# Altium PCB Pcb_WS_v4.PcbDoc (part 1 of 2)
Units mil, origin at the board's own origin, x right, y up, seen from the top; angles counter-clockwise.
Board outline 3890 x 3890 mil, 2 copper layers (Top Layer, Bottom Layer); 75 components, 61 nets, 248 pads, 370 vias.
Unrouted connection lines stored in the file: 31.
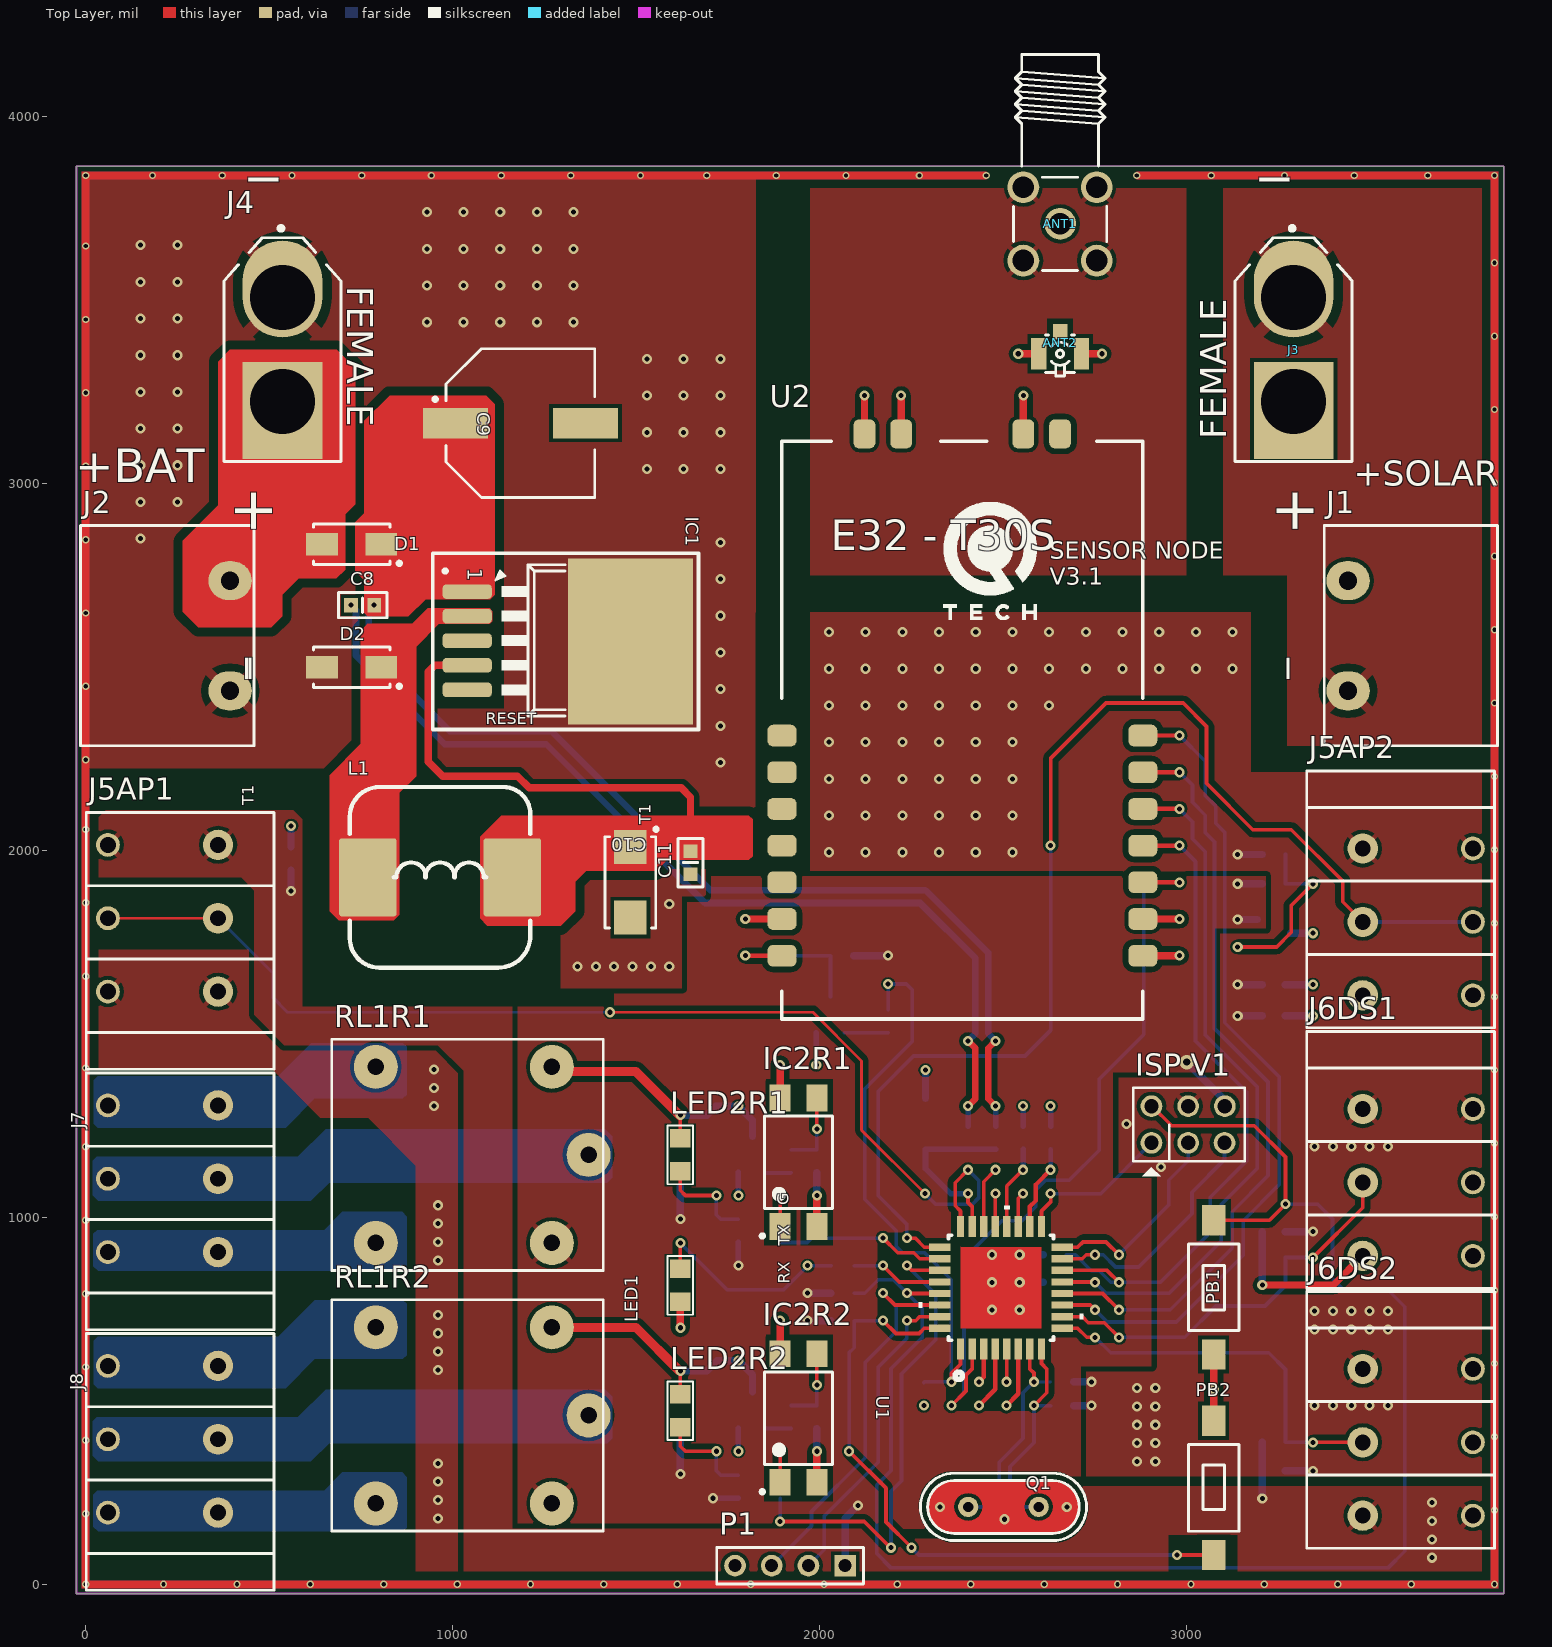
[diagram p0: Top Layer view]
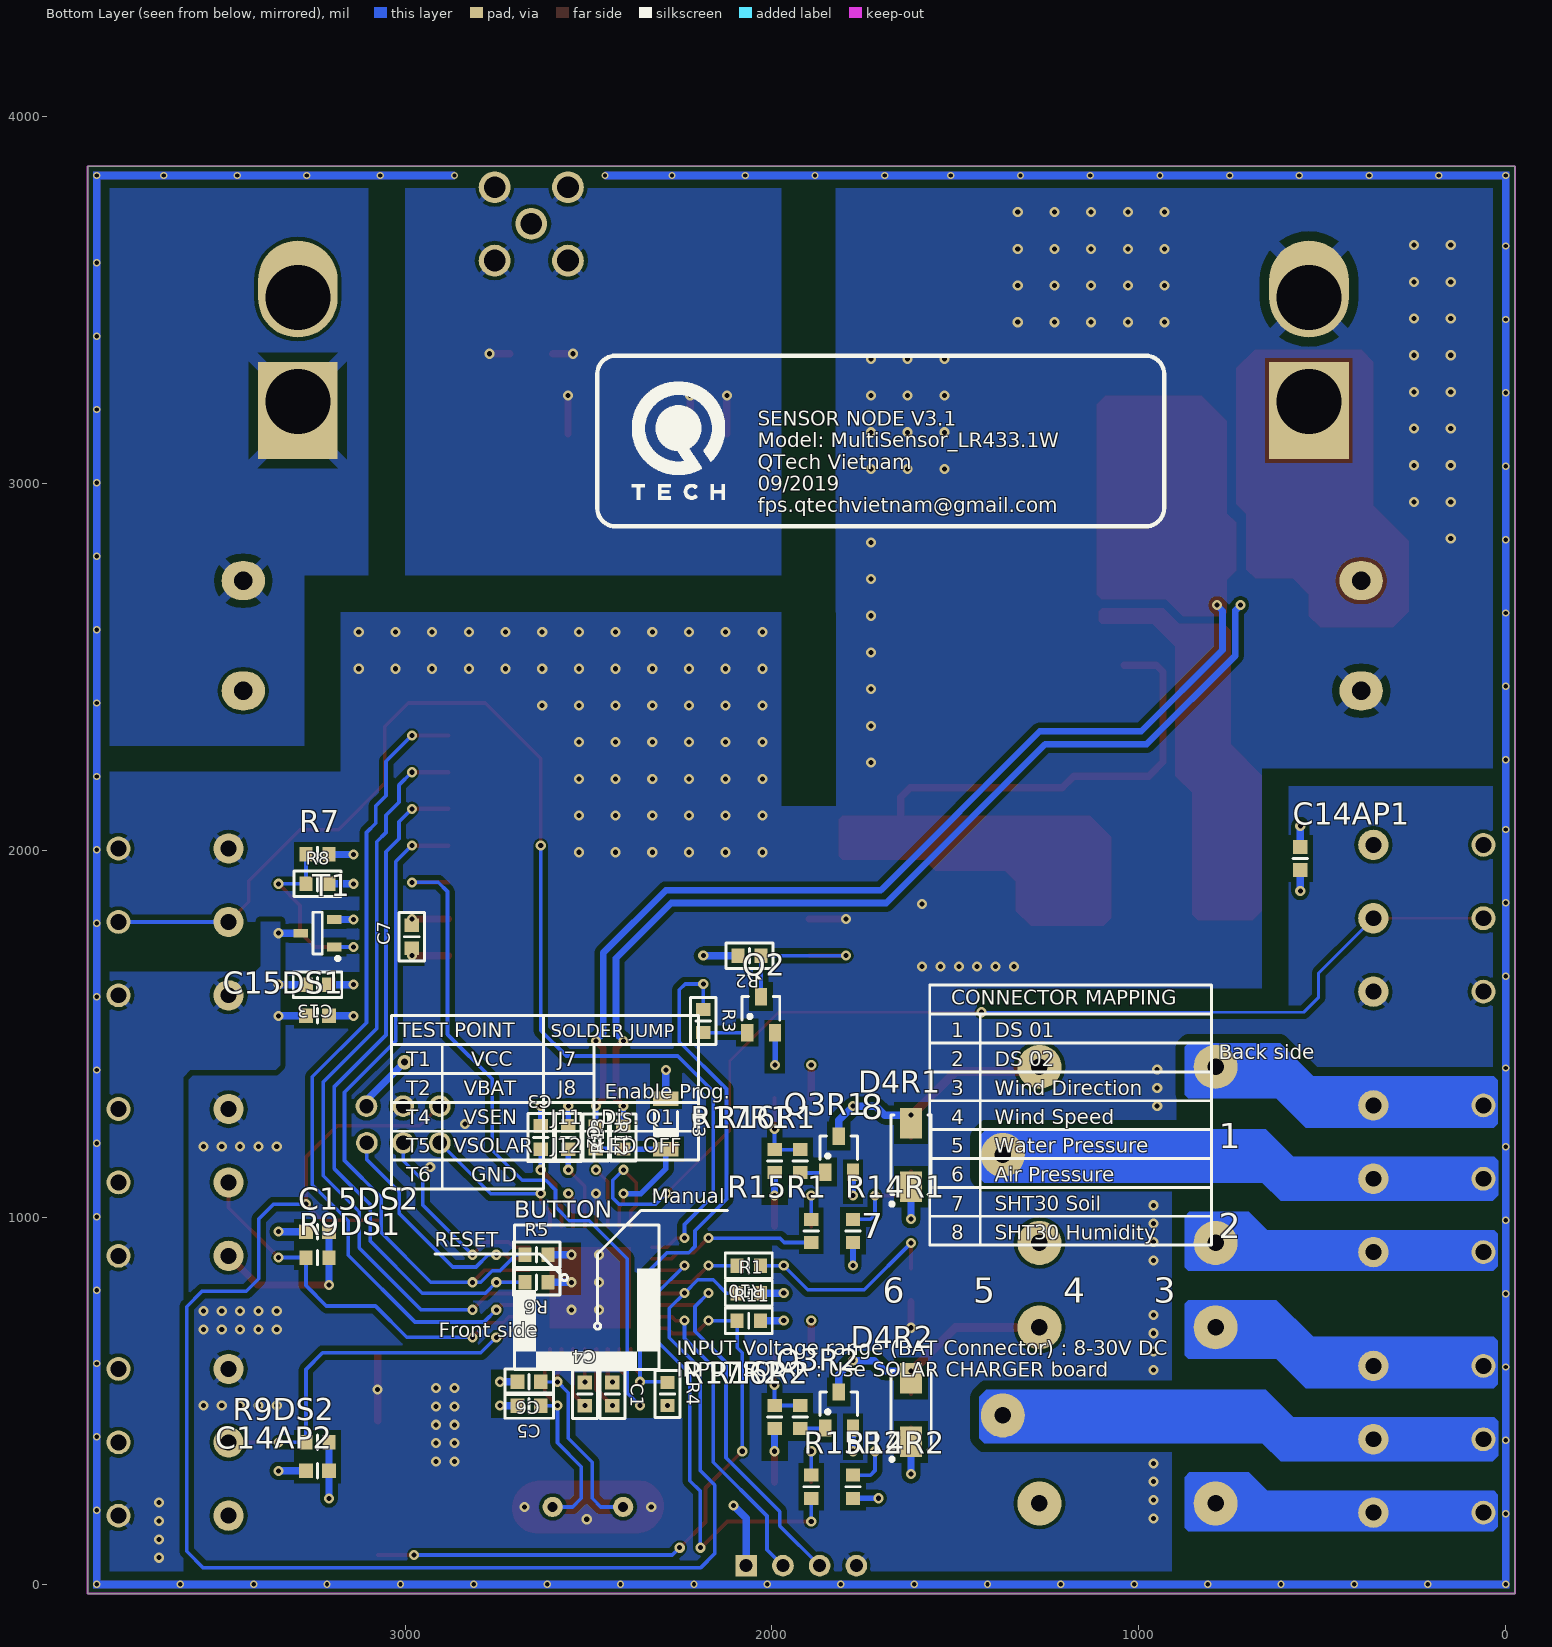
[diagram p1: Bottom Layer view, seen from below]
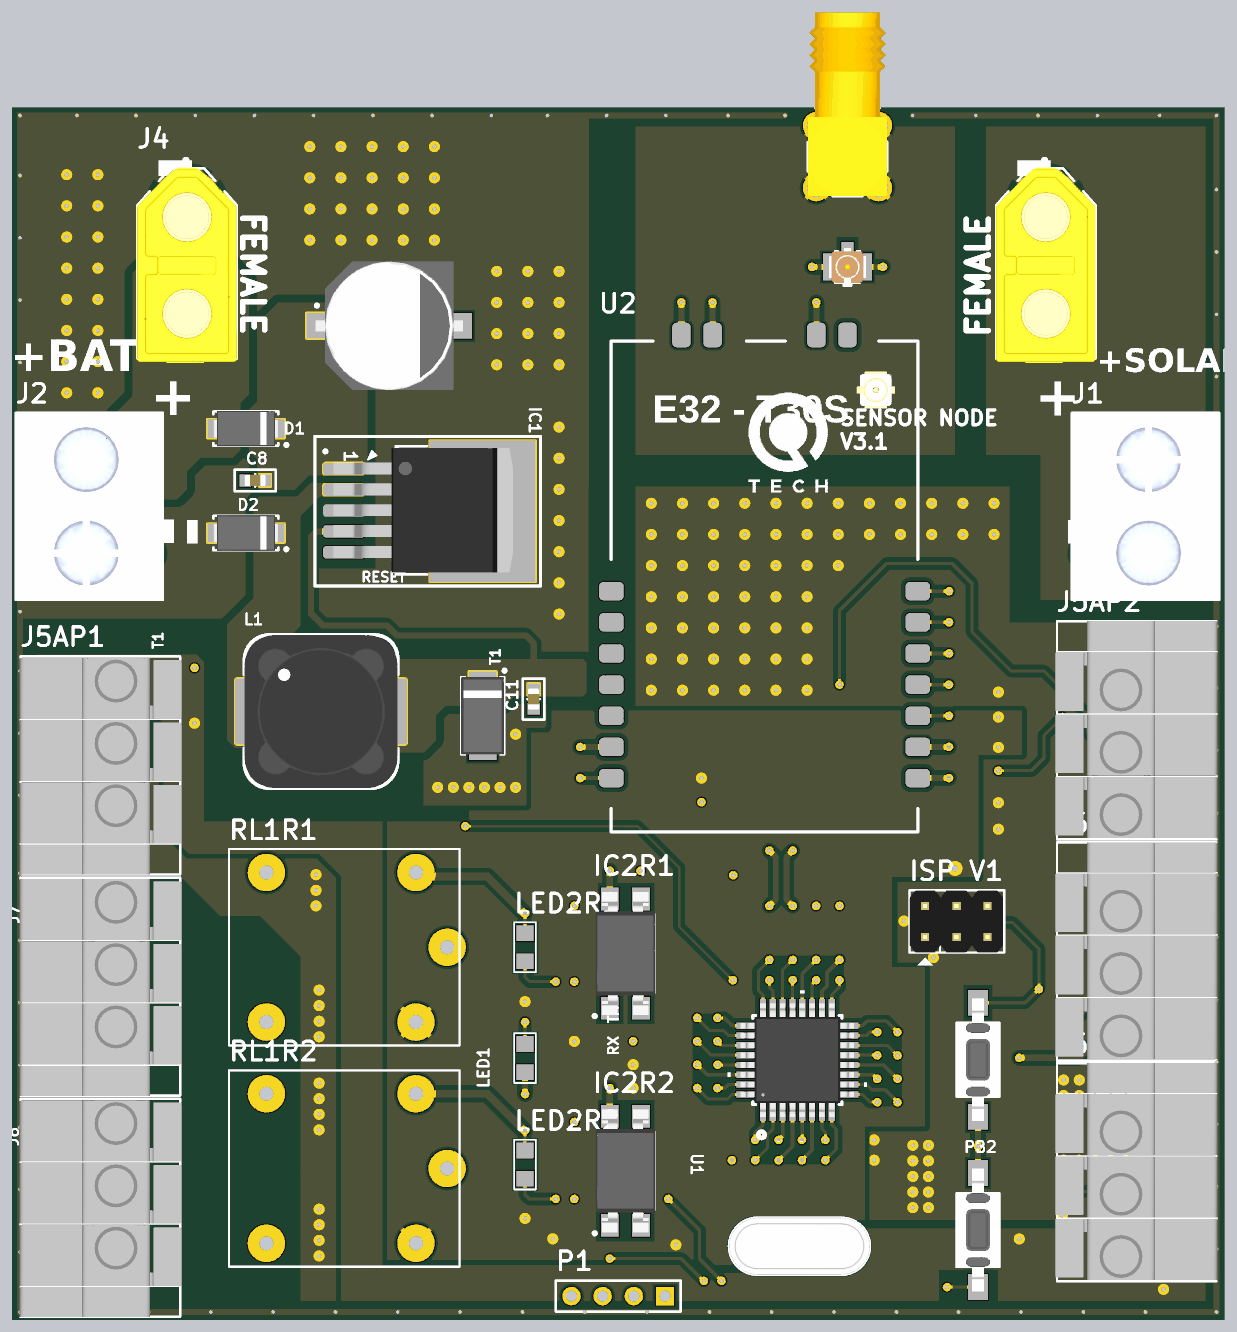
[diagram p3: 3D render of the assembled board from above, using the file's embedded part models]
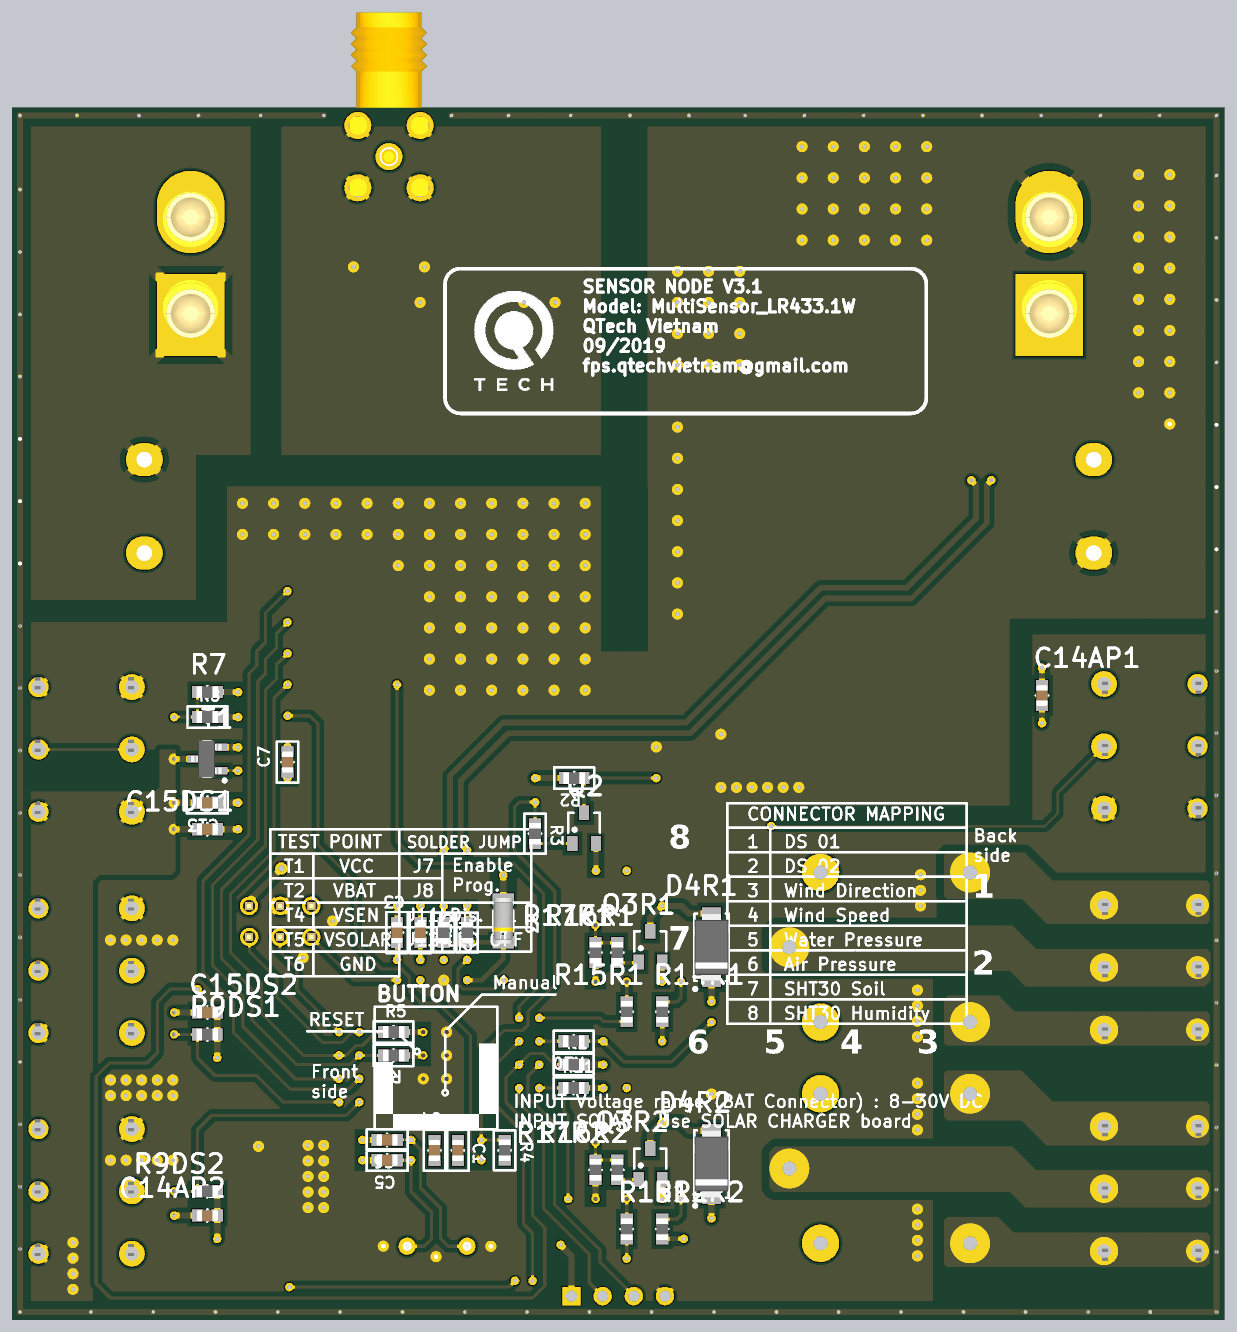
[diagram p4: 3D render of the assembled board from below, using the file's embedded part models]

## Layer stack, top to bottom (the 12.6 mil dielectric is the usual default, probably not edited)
Top Solder: solder mask 0.4, Solder Resist, Dk 3.5
Top Layer: signal copper 1.4
Dielectric 1: dielectric 12.6, FR-4, Dk 4.8
Bottom Layer: signal copper 1.4
Bottom Solder: solder mask 0.4, Solder Resist, Dk 3.5

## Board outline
-25,-25 -25,3865 3865,3865 3865,-25

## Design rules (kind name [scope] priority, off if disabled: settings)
Clearance Keep_Out [OnLayer('Keep-Out Layer')] p1: gap=5 ignorepadtopadclearanceinfootprint=FALSE
Clearance [All] p2: gap=10 ignorepadtopadclearanceinfootprint=FALSE except(5: Via-Poly Via-Region; 15: Track-Poly Track-Region SMDPad-Poly SMDPad-Region Poly-Poly; 25: Poly-Region)
ComponentClearance KF-conn_Clearance [InComponentClass('KF_conn') vs InComponentClass('KF_conn')] p1: gap=5 collisioncheckmode=3 verticalgap=0 showdistances=FALSE
ComponentClearance HS_Comp_Clearance [InComponentClass('HS_Comp') vs IsComponent] p2: gap=165 collisioncheckmode=3 verticalgap=0 showdistances=FALSE
ComponentClearance IC_Comp_Clearance [InComponentClass('IC_Comp') vs IsComponent] p3: gap=150 collisioncheckmode=3 verticalgap=0 showdistances=FALSE
ComponentClearance conn-th_Clearance [InComponentClass('conn-th') vs IsComponent and not InComponentClass('conn-th')] p4: gap=150 collisioncheckmode=3 verticalgap=0 showdistances=FALSE
ComponentClearance chip-ge_Clearance [InComponentClass('chip-ge') vs InAnyComponent] p5: gap=75 collisioncheckmode=3 verticalgap=0 showdistances=FALSE
ComponentClearance chip-0603_Clearance [InComponentClass('chip-0603') vs IsComponent] p6: gap=25 collisioncheckmode=3 verticalgap=0 showdistances=FALSE
PolygonConnect [All] p1: thpad.connectstyle=Relief thpad.reliefconductorwidth=13.78 thpad.reliefentries=4 thpad.polygonreliefangle="45 Angle" thpad.airgapwidth=10 smdpad.connectstyle=NoConnect smdpad.reliefconductorwidth=11.81 smdpad.reliefentries=4 smdpad.polygonreliefangle="45 Angle" smdpad.airgapwidth=10 via.connectstyle=Direct via.reliefconductorwidth=10 via.reliefentries=4 via.polygonreliefangle="90 Angle" via.airgapwidth=10
RoomDefinition Top_Level [InComponentClass('Top_Level')] p1: confinementstyle=ConfineIn formatcopy=TRUE lockcomponents=FALSE outline -1434.14,-1259.46 565.86,-1259.46 565.86,-259.46 -1434.14,-259.46
RoomDefinition R2 [InComponentClass('R2')] p2: confinementstyle=ConfineIn formatcopy=TRUE lockcomponents=FALSE outline -1434.14,-1259.46 565.86,-1259.46 565.86,-259.46 -1434.14,-259.46
RoomDefinition R1 [InComponentClass('R1')] p3: confinementstyle=ConfineIn formatcopy=TRUE lockcomponents=FALSE outline -1434.14,-1259.46 565.86,-1259.46 565.86,-259.46 -1434.14,-259.46
RoomDefinition PWR [InComponentClass('PWR')] p4: confinementstyle=ConfineIn formatcopy=TRUE lockcomponents=FALSE outline -1434.14,-1259.46 565.86,-1259.46 565.86,-259.46 -1434.14,-259.46
RoomDefinition Main [InComponentClass('Main')] p5: confinementstyle=ConfineIn formatcopy=TRUE lockcomponents=FALSE outline -1434.14,-1259.46 565.86,-1259.46 565.86,-259.46 -1434.14,-259.46
RoomDefinition Lora [InComponentClass('Lora')] p6: confinementstyle=ConfineIn formatcopy=TRUE lockcomponents=FALSE outline -1434.14,-1259.46 565.86,-1259.46 565.86,-259.46 -1434.14,-259.46
RoomDefinition DS2 [InComponentClass('DS2')] p7: confinementstyle=ConfineIn formatcopy=TRUE lockcomponents=FALSE outline -1434.14,-1259.46 565.86,-1259.46 565.86,-259.46 -1434.14,-259.46
RoomDefinition DS1 [InComponentClass('DS1')] p8: confinementstyle=ConfineIn formatcopy=TRUE lockcomponents=FALSE outline -1434.14,-1259.46 565.86,-1259.46 565.86,-259.46 -1434.14,-259.46
RoomDefinition AP2 [InComponentClass('AP2')] p9: confinementstyle=ConfineIn formatcopy=TRUE lockcomponents=FALSE outline -1434.14,-1259.46 565.86,-1259.46 565.86,-259.46 -1434.14,-259.46
RoomDefinition AP1 [InComponentClass('AP1')] p10: confinementstyle=ConfineIn formatcopy=TRUE lockcomponents=FALSE outline -1434.14,-1259.46 565.86,-1259.46 565.86,-259.46 -1434.14,-259.46
RoutingVias [All] p1: holewidth=13.78 width=27.56 viastyle="Through Hole" minholewidth=11.81 minwidth=23.62 maxholewidth=19.68 maxwidth=39.37
ShortCircuit [All] p1: allowed=TRUE
SolderMaskExpansion [All] p1: expansion=4 istentingtop=FALSE
Width [All] p1: maxlimit=196.85 minlimit=8 preferedwidth=10
28 further rules are at their usual default settings.

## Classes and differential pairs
component class KF_conn: J5AP1 J5AP2 J6DS1 J6DS2 J7 J8
component class HS_Comp: ANT1 ANT2 Q1
component class IC_Comp: IC1 IC2R1 IC2R2 L1 U1 U2
component class chip-ge: C9 C10 D1 D2 D4R1 D4R2
component class conn-th: "ISP V1" J1 J2 J3 J4 J5AP1 J5AP2 J6DS1 J6DS2 J7 J8 P1 PB1 PB2 RL1R1 RL1R2
component class chip-0603: C1 C2 C3 C4 C5 C6 C7 C8 C11 C13 C14AP1 C14AP2 C15DS1 C15DS2 D3 LED1 LED2R1 LED2R2 Q2 Q3R1 Q3R2 R1 R2 R3 R4 R5 R6 R7 R8 R9DS1 R9DS2 R10 R11 R12 R13 R14R1 R14R2 R15R1 R15R2 R16R1 R16R2 R17R1 R17R2 T1
channel class Sensor_DS18b20_1Wire: DS1 DS2
channel class Sensor_AirPressure_1Wire: AP1 AP2
channel class Relay: R1 R2
component class Top_Level: D3 J7 J8 LED1 P1 PB2 R10 R11 R12 R13
component class R2: D4R2 IC2R2 LED2R2 Q3R2 R14R2 R15R2 R16R2 R17R2 RL1R2
component class R1: D4R1 IC2R1 LED2R1 Q3R1 R14R1 R15R1 R16R1 R17R1 RL1R1
component class Main: C1 C2 C3 C4 C5 C6 "ISP V1" PB1 R1 U1
component class Lora: ANT1 ANT2 C7 Q2 R2 R3 R4 R5 R6 U2
component class DS2: C15DS2 J6DS2 R9DS2
component class DS1: C15DS1 J6DS1 R9DS1
component class AP2: C14AP2 J5AP2
component class AP1: C14AP1 J5AP1
component class PWR: C8 C9 C10 C11 C13 D1 D2 IC1 J1 J2 J3 J4 L1 R7 R8 T1

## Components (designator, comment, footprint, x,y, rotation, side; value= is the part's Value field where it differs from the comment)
ANT1 "Coax_1Female_1Shield" "HUBER-SUHNER_85 SMA-50-0-101/111 NE" 2655.84,3708 r90 top
ANT2 "U.FL" HIROSE_U.FL-R-SMT-1(10) 2655.84,3354 r180 top
C1 "100nF" CAPC1608X87N 2434.61,518.68 r90 bottom
C2 "100nF" CAPC1608X87N 2555,1217.82 r270 bottom
C3 "100nF" CAPC1608X87N 2630,1217.82 r90 bottom
C4 "100nF" CAPC1608X87N 2509.61,518.68 r90 bottom
C5 "100nF" CAPC1608X87N 2661.8,487.18 r0 bottom value=22pF
C6 "100nF" CAPC1608X87N 2661.8,552.18 r0 bottom value=22pF
C7 "100nF" CAPC1608X87N 2981.43,1765 r270 bottom
C8 "100nF" CAPC1608X87N 755,2668.89 r180 top
C9 "470uF" CAPAE1030X1020N 1185,3165 r0 top
C10 "100uF" CAPMP6032X280N 1485,1913.49 r270 top
C11 "100nF" CAPC1608X87N 1648.55,1967 r270 top
C13 "100nF" CAPC1608X87N 3238.5,1634.46 r180 bottom
C14AP1 "100nF" CAPC1608X87N 560,1978.5 r270 bottom (schematic designator C14)
C14AP2 "100nF" CAPC1608X87N 3238.5,309.46 r180 bottom (schematic designator C14)
C15DS1 "100nF" CAPC1608X87N 3238.5,1549.46 r0 bottom (schematic designator C15)
C15DS2 "100nF" CAPC1608X87N 3238.5,961.31 r180 bottom (schematic designator C15)
D1 "SS16" DIOM5127X229N 725,2835 r180 top
D2 "SS16" DIOM5127X229N 725,2500 r180 top
D3 "BZV55-B5V1" DIOMELF3515N 2289.08,1255.22 r90 bottom
D4R1 "BZG03C220" DIOM5326X230N 1620.86,1170.54 r90 bottom (schematic designator D4)
D4R2 "BZG03C220" DIOM5326X230N 1620.86,475 r90 bottom (schematic designator D4)
IC1 "LM2596" TO263-5 1040.04,2705.82 r270 top
IC2R1 "SFH6156-4" SOIC254P977X406-4N 1942.86,1150.54 r90 top (schematic designator IC2)
IC2R2 "SFH6156-4" SOIC254P977X406-4N 1942.86,453.26 r90 top (schematic designator IC2)
"ISP V1" "Connector 3x2" JP3x2 3005,1253.39 r0 top
J1 "CON KF7.62-2P" "CON KF7.62-2P" 3440.86,2585.54 r270 top locked
J2 "CON KF7.62-2P" "CON KF7.62-2P" 393.93,2585.54 r90 top locked
J3 "XT60-FM" XT60-FM 3292.32,3364.99 r270 top locked
J4 "XT60-FM" XT60-FM 536.41,3364.99 r270 top locked
J5AP1 "KF142V-3P" "CON KF142V-3P-5.08" 60.86,2015.54 r270 top (schematic designator J5)
J5AP2 "KF142V-3P" "CON KF142V-3P-5.08" 3780.86,1605.54 r90 top (schematic designator J5)
J6DS1 "KF142V-3P" "CON KF142V-3P-5.08" 3780.86,895.54 r90 top (schematic designator J6)
J6DS2 "KF142V-3P" "CON KF142V-3P-5.08" 3780.86,187.26 r90 top (schematic designator J6)
J7 "KF142V-3P" "CON KF142V-3P-5.08" 60.86,1305.54 r270 top
J8 "KF142V-3P" "CON KF142V-3P-5.08" 60.86,595.54 r270 top
L1 "33uH" L_SMD 769.25,1927 r90 top
LED1 "LED" L-0805 1620.86,815 r270 top value="LED 3 ly Single Colour"
LED2R1 "LED" L-0805 1620.86,1170.54 r90 top value="LED 3 ly Single Colour" (schematic designator LED2)
LED2R2 "LED" L-0805 1620.86,473.26 r90 top value="LED 3 ly Single Colour" (schematic designator LED2)
P1 "Header 4" HDR1X4 2070,51 r180 top
PB1 "Push Button" PB_TYCO_FSMSM 3074.53,809.62 r270 top
PB2 "Push Button" PB_TYCO_FSMSM 3074.53,263.07 r90 top
Q1 "20MHz" XTAL_HC-49/U 2501.55,211.12 r0 top
Q2 "C1815" SOT23-3 2030.2,1552.8 r180 bottom
Q3R1 "C1815" SOT23-3 1817.86,1172.59 r180 bottom (schematic designator Q3)
Q3R2 "C1815" SOT23-3 1817.86,475.31 r180 bottom (schematic designator Q3)
R1 "10k" RESC1608X55N 2063.21,793.79 r0 bottom
R2 "10k" RESC1608X55N 2061.5,1713.49 r0 bottom value=4k7
R3 "10k" RESC1608X55N 2187.06,1535.29 r270 bottom value=1k
R4 "10k" RESC1608X55N 2284.61,518.68 r90 bottom value=1k
R5 "4k7" RESC1608X55N 2641.17,898.39 r180 bottom value=10k
R6 "4k7" RESC1608X55N 2641.17,823.39 r180 bottom value=10k
R7 "1k" RESC1608X55N 3238.5,1989.46 r0 bottom
R8 "10k" RESC1608X55N 3238.5,1909.46 r0 bottom
R9DS1 "4k7" RESC1608X55N 3238.5,890.77 r180 bottom (schematic designator R9)
R9DS2 "4k7" RESC1608X55N 3238.5,387.26 r180 bottom (schematic designator R9)
R10 "10k" RESC1608X55N 2063.21,868.79 r180 bottom value=200
R11 "10k" RESC1608X55N 2063.21,718.79 r0 bottom
R12 "10k" RESC1608X55N 2480,1217.82 r270 bottom value=2M
R13 "10k" RESC1608X55N 2405,1217.82 r90 bottom value=1M
R14R1 "1k" RESC1608X55N 1779.06,963.52 r90 bottom value=200 (schematic designator R14)
R14R2 "1k" RESC1608X55N 1779.06,266.24 r90 bottom value=200 (schematic designator R14)
R15R1 "1k" RESC1608X55N 1892.86,963.52 r90 bottom (schematic designator R15)
R15R2 "1k" RESC1608X55N 1892.86,266.24 r90 bottom (schematic designator R15)
R16R1 "1k" RESC1608X55N 1922.86,1153.52 r270 bottom value=200 (schematic designator R16)
R16R2 "1k" RESC1608X55N 1922.86,456.24 r270 bottom value=200 (schematic designator R16)
R17R1 "10k" RESC1608X55N 1992.86,1153.52 r90 bottom (schematic designator R17)
R17R2 "10k" RESC1608X55N 1992.86,456.24 r90 bottom (schematic designator R17)
RL1R1 "Relay 10A/12V" RL_SPDT_10A 1370.86,1170.54 r180 top value="Relay SPDT, 10A, 12V" (schematic designator RL1)
RL1R2 "Relay 10A/12V" RL_SPDT_10A 1370.86,460.54 r180 top value="Relay SPDT, 10A, 12V" (schematic designator RL1)
T1 "BSH203" SOT95P230X110-3N 3238.5,1774.74 r0 bottom
U1 "ATmega328-AU" 32A_ATM-M 2494.8,808.59 r90 top
U2 "E32-T30S" E32-T30S 2881.43,3115.85 r180 top

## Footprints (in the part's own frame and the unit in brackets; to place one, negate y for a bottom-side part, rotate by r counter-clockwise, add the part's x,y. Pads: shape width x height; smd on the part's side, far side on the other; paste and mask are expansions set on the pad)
32A_ATM-M [mil]
  rect 58x20 smd: 1(-167,110.24) 2(-167,78.74) 3(-167,47.24) 4(-167,15.75) 5(-167,-15.75) 6(-167,-47.24) 7(-167,-78.74) 8(-167,-110.24) 17(167,-110.24) 18(167,-78.74) 19(167,-47.24) 20(167,-15.75) 21(167,15.75) 22(167,47.24) 23(167,78.74) 24(167,110.24)
  rect 20x58 smd: 9(-110.24,-167) 10(-78.74,-167) 11(-47.24,-167) 12(-15.75,-167) 13(15.75,-167) 14(47.24,-167) 15(78.74,-167) 16(110.24,-167) 25(110.24,167) 26(78.74,167) 27(47.24,167) 28(15.75,167) 29(-15.75,167) 30(-47.24,167) 31(-78.74,167) 32(-110.24,167)
  silkscreen extent -250,-224 224,224, body extent -182,-182 182,182, height 47
CAPAE1030X1020N [mm] "Capacitor, Aluminium Electrolytric, 10.3mm L X 10.3mm W X 10.2mm H, IPC Medium Density"
  rect 4.5x2.1 smd: 1(-4.5,0) 2(4.5,0)
  silkscreen extent -6.02,-5.15 5.15,5.15, body extent -6,-5.25 6,5.25, height 10.2
CAPC1608X87N [mm] "Chip Capacitor, Body 1.6x0.8mm IPC Medium Density"
  rect 0.95x1 smd: 1(-0.8,0) 2(0.8,0)
  silkscreen extent -1.68,-0.87 1.68,0.87, body extent -0.87,-0.47 0.88,0.48, height 0.87
CAPMP6032X280N [mm] "Capacitor, Polarized, Molded  Body 6.0x3.2mm, IPC Medium Density"
  rect 2.35x2.25 smd: 1(-2.45,0) 2(2.45,0)
  silkscreen extent -3.8,-1.75 3.15,1.9, body extent -3.15,-1.75 3.15,1.75, height 2.8
"CON KF7.62-2P" [mm]
  oval 2.7x3 hole 1.26: 1(-3.81,0) 2(3.81,0)
  silkscreen extent -7.62,-1.65 7.62,10.35, body extent -7.62,-1.65 7.62,10.35, height 12.4
"CON KF142V-3P-5.08" [mm]
  round 2.1 hole 1.1: 1(0,7.62) 2(5.08,7.62) 3(10.16,7.62)
  round 1.65 hole 1.1: 1(0,0) 2(5.08,0) 3(10.16,0)
  silkscreen extent -2.25,-1.5 15.53,11.5, body extent -2.14,-1.57 15.54,11.63, height 14.23
DIOM5127X229N [mm] "DO-214-AC/SMA Molded Diode, 2-Leads, Body 5.1x2.7mm, IPC Medium Density"
  rect 2.2x1.55 smd: 1(-2.05,0) 2(2.05,0)
  silkscreen extent -3.43,-1.4 2.65,1.45, body extent -2.67,-1.45 2.68,1.45, height 2.29
DIOM5326X230N [mm] "DO-214-AC/SMA Molded Diode, Body 5.3x2.6mm, IPC Medium Density"
  rect 2.1x1.55 smd: 1(-2.2,0) 2(2.2,0)
  silkscreen extent -3.52,-1.4 2.75,1.45, body extent -2.75,-1.4 2.75,1.4, height 2.3
DIOMELF3515N [mm] "SOD80C, MELF Diode, 2-Leads, Body 3.5x1.5mm, IPC Medium Density"
  rect 1x1.75 smd: 1(-1.75,0) 2(1.75,0)
  silkscreen extent -0.85,-0.8 0.85,0.8, body extent -1.85,-0.8 1.85,0.8, height 1.6
E32-T30S [mm] "Lora-EBYTE-21~30dBm-UART-SX1278-25x40mm"
  rrect50% 2x1.5 smd: 1(0,20.38) 2(0,22.92) 3(0,25.46) 4(0,28) 5(0,30.54) 6(0,33.08) 7(0,35.62) 8(24.98,35.62) 9(24.98,33.08) 10(24.98,30.54) 11(24.98,28) 12(24.98,25.46) 13(24.98,22.92) 14(24.98,20.38)
  rrect50% 1.5x2 smd: 15(19.27,-0.5) 16(16.73,-0.5) 17(8.27,-0.5) 18(5.73,-0.5)
  silkscreen extent 0,0 25,40, body extent 0,0 25,40, height 3.5
HDR1X4 [mm] "Connector; Header; 4 Position"
  rect 1.5x1.5 hole 0.9: 1(0,0)
  round 1.5 hole 0.9: 2(2.54,0) 3(5.08,0) 4(7.62,0)
  silkscreen extent -1.27,-1.27 8.89,1.27
HIROSE_U.FL-R-SMT-1(10) [mm] "Up to 6GHz Ultra Small Surface Mount Male Coaxial Connectors U.FL Series"
  rect 1x1.05 smd: 1(0,-1.525)
  rect 1.05x2.2 smd: 2(-1.475,0) 2(1.475,0)
  silkscreen extent -1,-1.3 1,1.55, body extent -1.5,-1.55 1.5,1.55, height 1.25
"HUBER-SUHNER_85 SMA-50-0-101/111 NE" [mm] "50 Ohm SMA Right Angle PCB Jack"
  round 2.2 hole 1.5: 1(0,0) 2(-2.54,-2.54) 2(-2.54,2.54) 2(2.54,-2.54) 2(2.54,2.54)
  silkscreen extent -3.23,-3.23 11.73,3.23, body extent -3.23,-3.23 11.73,3.23, height 9.6
JP3x2 [mm] "Connector 3x2"
  round 1.5 hole 1: 1(-2.54,-1.27) 2(0,-1.27) 3(2.515,-1.27) 4(-2.54,1.27) 5(0,1.27) 6(2.54,1.27)
  silkscreen extent -3.81,-3.58 3.91,2.54, body extent -3.81,-2.54 3.81,2.54, height 8.52
L-0805 [mil] "Compoment SMD 80x50mil"
  rect 50x55 smd: 1(-45,0) 2(45,0)
  silkscreen extent -80,-35 80,35, body extent -50,-20 50,20, height 43
L_SMD [mm]
  rrect10% 5.4x4 smd mask+0.1: 1(0,0) 2(0,-10)
  silkscreen extent -6.25,-11.25 6.25,1.25, body extent -6.25,-11.25 6.25,1.25, height 6.7
PB_TYCO_FSMSM [mm] "Body 3.5x6.0mm, Pushbutton Switch,  TYCO FSMSM Serie"
  rect 2.1x1.6 smd: 1(-4.65,0) 2(4.65,0)
  silkscreen extent -3,-1.75 3,1.75, body extent -5,-1.75 5,1.75, height 4.3
RESC1608X55N [mm] "Chip Resistor, EIA 0603, Metric 1608, Body 1.6x0.8mm, IPC Medium Density"
  rect 0.9x1 smd: 1(-0.8,0) 2(0.8,0)
  silkscreen extent -1.63,-0.87 1.63,0.87, body extent -0.87,-0.47 0.88,0.48, height 0.55
RL_SPDT_10A [mil] "Relay SPDT, 5 pin, 10A,W 650mil, L 800mil, H 800mil"
  round 120 hole 45: 1(0,0) 2(580,240) 3(580,-240) 4(100,-240) 5(100,240)
  silkscreen extent -40,-315 700,315
SOIC254P977X406-4N [mm] "SOIC, 2.54mm pitch; 4 pin, 6.65mm W X 4.69mm L, IPC Medium Density"
  rect 1.85x1.45 smd: 1(-4.45,1.27) 2(-4.45,-1.27) 3(4.45,-1.27) 4(4.45,1.27)
  silkscreen extent -5.22,-2.35 3.2,2.62, body extent -5.01,-2.41 5.02,2.42, height 4.06
SOT23-3 [mm] "SOT 23"
  rect 0.85x1.2 smd: 1(-0.94,-1.245) 2(0.985,-1.25) 3(0.005,1.25)
  silkscreen extent -1.29,-0.38 1.31,1.25, body extent -1.5,-1.5 1.52,1.5, height 1.27
SOT95P230X110-3N [mm] "SOT23, 3 pin, Pitch 0.95mm - 1.3mm W X 2.9mm L X 1.1mm H, IPC Medium Density"
  rect 1x0.6 smd: 1(-1.15,0.95) 2(-1.15,-0.95) 3(1.15,0)
  silkscreen extent -1.52,-1.45 0.33,1.87, body extent -1.17,-1.5 1.33,1.5, height 1.1
TO263-5 [mm]
  rrect50% 1x3.4 smd: 1(0,0) 2(1.7,0) 4(5.1,0) 5(6.8,0)
  rrect50% 1x3.4 smd mask+0: 3(3.4,0)
  rect 11.5x8.634 smd: 6(3.45,11.302)
  silkscreen extent -2.66,-2.38 9.54,16.02, body extent -1.71,-0.87 8.45,13.77, height 4.57
XT60-FM [mm]
  oval 6.716x5.516 hole 4.5 copper offset -0.6,0: 1(-3.6,0)
  rect 6.716x5.516 hole 4.5 copper offset 0.6,0: 2(3.6,0)
  silkscreen extent -8.55,-4.05 7.75,4.05, body extent -7.81,-4.07 8.12,4.06, height 15.5
XTAL_HC-49/U [mm] "HC-49/U Leaded Cristal, Body 11.05x4.8mm; Pitch 4.88mm"
  round 1.4 hole 0.7: 1(-2.44,0) 2(2.44,0)
  silkscreen extent -5.75,-2.33 5.75,2.33, body extent -5.75,-2.33 5.75,2.33, height 3.5

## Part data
ANT1: library part HUBER-SUHNER_85_SMA-50-0-101/111_NE, Manufacturer=HUBER+SUHNER, Manufacturer Part Number=85_SMA-50-0-101/111_NE
ANT2: library part HIROSE_U.FL-R-SMT-1(10), Manufacturer="HIROSE (HRS)", Manufacturer Part Number=U.FL-R-SMT-1(10)
C1 C2 C3 C4 C7 C8 C11 C13 C14AP1 C14AP2 C15DS1 C15DS2: library part CC0603_100NF_50V_10%_X7R, "Non-polarised capacitor", Case=0603, Manufacturer=GENERIC, Manufacturer1 ComponentHeight=0.87mm, Manufacturer1 Example=PHYCOMP, Manufacturer1 Part Number=223858615649, Tolerance=±10%, Voltage=50V
C5 C6: library part CC0603_22PF_50V_5%_NP0, "Non-polarised capacitor", Case=0603, Manufacturer=GENERIC, Manufacturer1 ComponentHeight=0.87mm, Manufacturer1 Example=PHYCOMP, Manufacturer1 Part Number=223886715229, Tolerance=±5%, Voltage=50V
C9: library part CAE1030-1020_470UF_25V_20%, "Polarised capacitor", Case=G, Manufacturer=GENERIC, Manufacturer1 ComponentHeight=10.2mm, Manufacturer1 Example=PANASONIC, Manufacturer1 Part Number=EEEFK1E471AP, Tolerance=±20%, Voltage=25V
C10: library part CTE6032-28_100UF_6.3V_10%_LESR0075, "Polarised capacitor", Case=C, Manufacturer=GENERIC, Manufacturer1 ComponentHeight=2.8mm, Manufacturer1 Example=AVX, Manufacturer1 Part Number=TPSC107K006R0075, Tolerance=±10%, Voltage=6.3V
D1 D2: "Schottky Diode", Case=DO-214AC, Manufacturer="VISHAY GENERAL SEMICONDUCTOR", Power=1A, Voltage=60V
D3: "Zener Diode", Case=SOD-80C, Manufacturer="NXP SEMICONDUCTORS", Power=500mW, Voltage=5V1
D4R1 D4R2: "Zener Diode", Case=DO-214AC, Manufacturer="VISHAY SEMICONDUCTOR", Power=1.25W, Voltage=220V
IC1: library part LM2596-5V
IC2R1 IC2R2: "Single Optocoupler", Case=SOIC4, Manufacturer="VISHAY SEMICONDUCTORS"
"ISP V1": library part JP3x2
J3 J4: Package="Package Analog Devices"
J5AP1 J5AP2 J6DS1 J6DS2 J7 J8: library part "CON KF142V-3P-5.08", "CON KF142V-3P-5.08"
L1: library part "L_SMD 33uH"
LED1 LED2R1 LED2R2: "LED Single colour Green and Red"
P1: "Header, 4-Pin"
PB1 PB2: "Push-Button Switch SPDT", Manufacturer="TYCO ELECTRONICS", Manufacturer Part Number="FSMSM or 1437566-3", Part Number=PB_TYCO_FSMSM
Q1: library part XTAL_20MHZ_AEL_HC-49/U, "Quartz Crystal", Manufacturer="AEL CRYSTALS", Manufacturer Part Number=X20M000000L010
Q2 Q3R1 Q3R2: library part 2SC1815, PSpiceTemplate="Q^@REFDES %c %b %e @MODEL"
R1 R5 R6 R8 R11 R17R1 R17R2: library part R0603_10K_1%_0.1W_100PPM, "Resistor - 1%", Case=0603, Manufacturer=GENERIC, Manufacturer1 ComponentHeight=0.55mm, Manufacturer1 Example="NIC COMPONENT", Manufacturer1 Part Number=NRC06F1002TRF, Power=0.1W, Tolerance=±1%
R2 R9DS1 R9DS2: library part R0603_4K7_1%_0.1W_100PPM, "Resistor - 1%", Case=0603, Manufacturer=GENERIC, Manufacturer1 ComponentHeight=0.55mm, Manufacturer1 Example="NIC COMPONENT", Manufacturer1 Part Number=NRC06F4701TRF, Power=0.1W, Tolerance=±1%
R3 R4 R7 R15R1 R15R2: library part R0603_1K_1%_0.1W_100PPM, "Resistor - 1%", Case=0603, Manufacturer=GENERIC, Manufacturer1 ComponentHeight=0.55mm, Manufacturer1 Example="NIC COMPONENT", Manufacturer1 Part Number=NRC06F1001TRF, Power=0.1W, Tolerance=±1%
R10 R14R1 R14R2 R16R1 R16R2: library part R0603_200R_1%_0.1W_100PPM, "Resistor - 1%", Case=0603, Manufacturer=GENERIC, Manufacturer1 ComponentHeight=0.55mm, Manufacturer1 Example="NIC COMPONENT", Manufacturer1 Part Number=NRC06F2000TRF, Power=0.1W, Tolerance=±1%
R12: library part R0603_2M_1%_0.1W_100PPM, "Resistor - 1%", Case=0603, Manufacturer=GENERIC, Manufacturer1 ComponentHeight=0.55mm, Manufacturer1 Example="NIC COMPONENT", Manufacturer1 Part Number=NRC06F2004TRF, Power=0.1W, Tolerance=±1%
R13: library part R0603_1M_1%_0.1W_100PPM, "Resistor - 1%", Case=0603, Manufacturer=GENERIC, Manufacturer1 ComponentHeight=0.55mm, Manufacturer1 Example="NIC COMPONENT", Manufacturer1 Part Number=NRC06F1004TRF, Power=0.1W, Tolerance=±1%
RL1R1 RL1R2: library part "Relay 1", "Relay SPDT,10A - 12VDC 5 Pin"
T1: "P-CHANNEL MOSFET WITH DIODE", Case=SOT23-3, Manufacturer="NXP SEMICONDUCTORS"
U1: "8-bit AVR Microcontroller, 32KB Flash, 1KB EEPROM, 2KB SRAM, 32-pin TQFP, Industrial Grade (-40°C to 85°C)", Supplier Part Number 1=ATMEGA328-AU-ND
U2: library part E32-433T30S, "Lora Ebyte E32-T30S Module"

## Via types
v1: diameter 27.56, hole 13.78, Top Layer to Bottom Layer, 293 vias
v2: diameter 20, hole 11.81, Top Layer to Bottom Layer, tented both sides, 76 vias
v3: diameter 39.37, hole 19.68, Top Layer to Bottom Layer, 1 vias

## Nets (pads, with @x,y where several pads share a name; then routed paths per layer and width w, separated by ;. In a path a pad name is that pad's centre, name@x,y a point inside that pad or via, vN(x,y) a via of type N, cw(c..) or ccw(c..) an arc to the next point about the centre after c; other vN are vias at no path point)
ANT_M: U2.18
ANT_M1: ANT1.1 ANT2.1
AREF: C2.2 U1.20 | length 229.1
  Top Layer w10: U1.20@2510.55,975.59 2510.55,1085.55 v1(2555,1130)
  Bottom Layer w15: v1(2555,1130) C2.2@2555,1186.32
AUX: U1.2 U2.5 | length 2073.6
  Top Layer w10: v1(2359.61,487.18) 2399.61,527.18 2399.61,570.81 2416.06,587.26 U1.2@2416.06,641.59
  Top Layer w12: U2.5@2881.43,1913.49 v1(2981.43,1913.49)
  Bottom Layer w10: v1(2359.61,487.18) 2394,521.58 2394,887.7 2497.75,991.44 2552.2,991.44 2589.73,1028.98 2589.73,1074.94 2616.01,1101.22 2680.43,1101.22 2762.28,1183.07 2762.28,1377.28 2884,1499 2884,1888.3 2909.19,1913.49 v1(2981.43,1913.49)
BAT-VSEN: C8.1 C9.1 D1.1 IC1.1 R12.1 | length 2654.9
  Top Layer w18: v1(2480,1303.39) 2460,1323.39 2460,1352.69 2460,1461 v1(2480,1481)
  Bottom Layer w15: R12.1@2480,1249.32 v1(2480,1303.39)
  Bottom Layer w18: v1(786.5,2668.89) 786.5,2668.06 772,2653.57 772,2546.24 993.24,2325 1270,2325 1703,1892 2288.83,1892 2460,1720.83 2460,1501.7 2480,1481.7 v1(2480,1481)
BAT-VSEN-Q: D3.1 R12.2 R13.1 U1.23 | length 482.1
  Top Layer w10: v1(2405,1065) 2405,1040.98 2416.06,1029.92 U1.23@2416.06,975.59
  Bottom Layer w15: v1(2405,1065) 2357.4,1065 2289.08,1133.32 D3.1@2289.08,1186.32 R13.1@2405,1186.32 R12.2@2480,1186.32
CLOSE1: J7.3 RL1R1.2
CLOSE2: J8.3 RL1R2.2
COM1: J7.2 RL1R1.1
COM2: J8.2 RL1R2.1
DATA-AP1: J5AP1.2 U1.24 | length 3115.9
  Top Layer w8: J5AP1.2@60.86,1815.54 J5AP1.2@360.86,1815.54 ; v1(1429.34,1559.37) 1982.1,1559.37 2115,1426.48 2115,1237.85 v1(2287.85,1065)
  Top Layer w10: U1.24@2384.57,975.59 2384.57,1017.43 2370,1032 2370,1095 v1(2405,1130)
  Bottom Layer w8: J5AP1.2@360.86,1815.54 510,1666.4 510,1600 550.63,1559.37 v1(1429.34,1559.37)
  Bottom Layer w10: v1(2287.85,1065) 2316.63,1036.22 2416.92,1036.22 2433.78,1053.08 2433.78,1101.22 v1(2405,1130)
DATA-AP2: J5AP2.2 U1.25 | length 3396.6
  Top Layer w10: v1(2238.39,943.79) 2261,943.79 2285.96,918.83 U1.25@2327.8,918.83 ; v1(2630,2013.49) 2630,2250.9 2781.1,2402 2991.45,2402 3055,2338.45 3055,2183.21 3181.21,2057 3286.19,2057 3426.23,1916.96 3426.23,1860.17 J5AP2.2@3480.86,1805.54
  Bottom Layer w10: v1(2238.39,943.79) 2238.39,980.82 2160,1059.21 2160,1343.51 2256.49,1440 2560.15,1440 2630,1509.85 v1(2630,2013.49) ; J5AP2.2@3480.86,1805.54 J5AP2.2@3780.86,1805.54
DATA-DS1: J6DS1.2 R9DS1.1 U1.10 | length 1102.4
  Top Layer w10: U1.10@2661.8,729.85 2716.13,729.85 2732.59,713.39 2776.21,713.39 v1(2816.21,673.39) ; v1(3345,890.77) 3480.86,1026.63 J6DS1.2@3480.86,1095.54
  Bottom Layer w10: v1(2816.21,673.39) 2995.39,673.39 3080.7,758.71 3214.32,758.71 3270,814.39 R9DS1.1@3270,890.77 v1(3345,890.77)
DATA-DS2: J6DS2.2 R9DS2.1 U1.9 | length 1064.1
  Top Layer w10: U1.9@2661.8,698.35 2703.65,698.35 2728.61,673.39 v1(2751.21,673.39) ; v1(3345,387.26) J6DS2.2@3480.86,387.26
  Bottom Layer w10: v1(2751.21,673.39) 2793.61,631 3224.66,631 3270,585.66 R9DS2.1@3270,387.26 v1(3345,387.26)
